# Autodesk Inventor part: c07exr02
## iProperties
Shininess: 77.0
Length Units: 11269
Angle Units: 11279
Time Units: 11290
Mass Units: 11283
Length Display Precision: 3
Angle Display Precision: 2
Created: 2002-01
Part Number: c07exr02
Document SubType Name: Modeling
Designer: ***
Density: 1 g/cm^3
Density: 0.0
Volumn: 0.0
Area: 0.0
PropertySet Name: Model Information
Control State: 0
Master: False
Checked Out: False
Author: ***
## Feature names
1. Extrusion1
2. Fillet1
3. Extrusion2
4. Extrusion3
5. Chamfer1
